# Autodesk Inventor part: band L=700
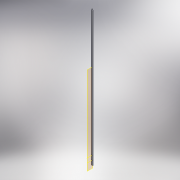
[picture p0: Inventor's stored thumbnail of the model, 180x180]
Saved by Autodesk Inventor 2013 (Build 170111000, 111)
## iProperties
Shininess: 25.0
Length Units: 11269
Angle Units: 11279
Time Units: 11290
Mass Units: 11283
Length Display Precision: 3
Angle Display Precision: 2
Created: 2002-03
Part Number: band L=700
Material: Steel, Mild
Document SubType Name: Modeling
Designer: =<Author>
Density: 7.86 g/cm^3
Description: =<Part Number>
Density: 7.86
Volumn: 11.117103732848953
Area: 86.2699198526635
PropertySet Name: Model Information
Control State: 0
Master: False
Checked Out: True
Checked Out Date: 2008-10-15
Last Check In Date: 2008-10-15
Author: LAlexey
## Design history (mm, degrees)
sketch "Sketch1"
  geometry: L1 (-21.168, 14.72)-(-13.768, 14.72); L2 (-13.768, 14.72)-(-13.768, 10.92); L3 (-13.768, 10.92)-(-21.168, 10.92); L4 (-21.168, 10.92)-(-21.168, 14.72)
  constraints: 8 end point, 2 parallel, 1 horizontal, 1 perpendicular
  dimensions: "d2" = 3.8 distance of L3.end L1.start; "d3" = 7.4 distance of L1.start L1.end
extrude "Extrusion1" new body sketch "Sketch1" distance "d0" = 630; taper "d1" = 0 deg
fillet "Fillet1" dims "d4" = 1
sketch "Sketch2"
  geometry: L1 (-13.768, 13.72)-(-13.768, 11.92) reference; L2 (-20.168, 14.72)-(-14.768, 14.72) reference; C1 r 1.5 at (-17.468, 12.82)
  constraints: 1 centre point
  dimensions: "d5" = 3 diameter of C1; "d6" = 1.9 distance from line of L2 C1.centre; "d7" = 3.7 distance from line of C1.centre L1
extrude "Extrusion2" join sketch "Sketch2" distance "d8" = 5; taper "d9" = 0 deg
sketch "Sketch3"
  geometry: L1 (-5.4, 0)-(0, 0) reference; L2 (0, 630)-(0, 0) reference; L3 (-5.4, 630)-(0, 630) reference; L4 (-5.4, 0)-(-5.4, 630) reference; C1 r 2 at (-2.91, 590); C2 r 2 at (-2.895, 610)
  constraints: 2 centre point, 1 equal radius
  dimensions: "d10" = 4 diameter of C1; "d12" = 19.99999 distance of C2.centre C1.centre; "d13" = 590 distance from line of L1 C1.centre
extrude "Extrusion3" cut sketch "Sketch3" distance "d14" = 5; taper "d15" = 0 deg
workaxis "Work Axis1"
workaxis "Work Axis2"
workplane "Work Plane1"
body "Solid1"
